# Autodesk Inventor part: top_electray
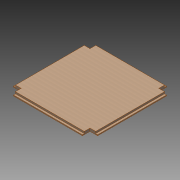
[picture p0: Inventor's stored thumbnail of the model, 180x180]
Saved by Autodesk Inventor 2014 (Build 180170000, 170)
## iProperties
Created: 2014-05
Part Number: top_electray
Material: Maple
Document SubType Name: Modeling
Designer: t_emanb
Density: 1 g/cm^3
Appearance: Maple - Solid Natural Medium Gloss
Author: t_emanb
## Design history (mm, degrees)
sketch "Sketch1"
  geometry: L1 (0, 0)-(558.8, 0); L2 (558.8, 0)-(558.8, 558.8); L3 (558.8, 558.8)-(0, 558.8); L4 (0, 558.8)-(0, 0)
  constraints: 8 end point, 2 parallel, 1 horizontal, 1 perpendicular
  dimensions: "d0" = 558.8 distance of L1.start L1.end; "d1" = 558.8 distance of L3.end L1.start (= d0)
extrude "Extrusion1" new body sketch "Sketch1" distance "d2" = 19.05; taper "d3" = 0 deg
sketch "Sketch2"
  geometry: L1 (0, 0)-(-558.8, 0) reference; L2 (-558.8, 0)-(-558.8, -558.8) reference; L3 (-558.8, -558.8)-(0, -558.8) reference; L4 (0, -558.8)-(0, 0) reference; L5 (-508, 0)-(-508, -50.8); L6 (-508, -50.8)-(-558.8, -50.8); L7 (-50.8, 0)-(-50.8, -50.8); L8 (-50.8, -50.8)-(0, -50.8); L9 (-50.8, -558.8)-(-50.8, -508); L10 (-50.8, -508)-(0, -508); L11 (-558.8, -508)-(-508, -508); L12 (-508, -508)-(-508, -558.8); L13 (-279.4, 0)-(-279.4, -558.8); L14 (-558.8, -279.4)-(0, -279.4)
  constraints: 20 end point, 8 point on line, 6 perpendicular, 5 collinear, 4 midpoint, 1 parallel, 2 other
  dimensions: "d4" = 457.2 distance between parallel lines of L8 L10; "d5" = 457.2 distance between parallel lines of L7 L5
extrude "Extrusion2" cut sketch "Sketch2" stored distance "d6" = 25.4; taper "d7" = 0 deg
sketch "Sketch3"
  geometry: L1 (0, 0)-(50.8, 0) reference; L2 (0, -19.05)-(0, 0) reference; L3 (0, -12.7)-(12.7, -12.7); L4 (12.7, -12.7)-(12.7, 0); 1 further point
  constraints: 4 end point, 2 perpendicular, 2 point on line
  dimensions: "d8" = 12.7 distance of L3.end L4.end; "d9" = 12.7 distance of L3.start L3.end
extrude "Extrusion3" cut sketch "Sketch3" stored distance "d10" = 25.4; taper "d11" = 0 deg
sketch "Sketch4"
  geometry: L1 (50.8, 0)-(50.8, -19.05) reference; L2 (0, 0)-(50.8, 0) reference; L3 (0, 0)-(0, -19.05) reference; L4 (38.1, 0)-(38.1, -12.7); L5 (38.1, -12.7)-(50.8, -12.7); 1 further point
  constraints: 4 end point, 2 point on line, 1 midpoint, 1 parallel, 1 perpendicular
  dimensions: "d12" = 12.7 distance of L4.start L4.end; "d16" = 12.7 distance of L4.end L5.end
extrude "Extrusion4" cut sketch "Sketch4" stored distance "d14" = 25.4; taper "d15" = 0 deg
workplane "Work Plane1"
workplane "Work Plane2"
mirror "Mirror1"
mirror "Mirror2"
body "Solid1"
